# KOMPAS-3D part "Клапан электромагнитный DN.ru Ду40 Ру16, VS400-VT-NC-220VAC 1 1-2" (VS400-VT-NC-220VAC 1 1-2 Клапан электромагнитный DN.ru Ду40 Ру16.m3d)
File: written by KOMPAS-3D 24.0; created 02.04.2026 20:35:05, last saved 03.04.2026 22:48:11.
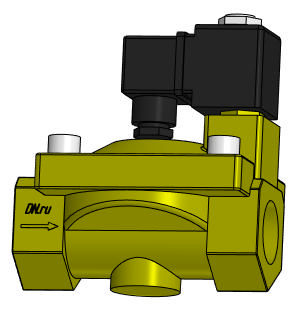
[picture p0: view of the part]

Document properties: Автор: artio; Полное имя файла: C:\Users\artio\OneDrive\Рабочий стол\Клапан электромагнитный DN.ru\VS400-VT-NC\VS400-VT-NC-220VAC 1 1-2 Клапан электромагнитный DN.ru Ду40 Ру16.m3d

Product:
- Body: Тело 1  | qty 1
    Масса: 4.144257
- Part/product: Клапан электромагнитный DN.ru Ду40 Ру16  | designation VS400-VT-NC-220VAC 1 1-2
    Масса: 2.321
    Раздел спецификации: Прочие изделия
    Примечание: D130-04702
    additional columns: ef56311e-7521-43dc-8291-0e6108b3d81d; VS400-ET-NC-220VAC 1 1-2; artio; c; Шероховатость не задана; Да

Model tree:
1. Операция без истории:1

Expressions: VS400-VT-NC-220VAC 1 1-2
